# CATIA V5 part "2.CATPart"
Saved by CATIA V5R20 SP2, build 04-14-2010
Part number: 2
Bounding box of the stored display mesh (mm): x -150 to 150, y -550 to 106.066, z -75 to 75
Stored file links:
  C:\Users\Orange\Desktop\Assembly Design-14\2.CATPart
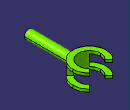
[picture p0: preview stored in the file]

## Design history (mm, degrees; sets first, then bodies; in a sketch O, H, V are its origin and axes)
Body1 (main body)
  Sketch1 on xy-plane, origin (0, 0, 0), H (1, 0, 0), V (0, 1, 0)
    circle A1 centre (0, 0) radius 150
    circle A2 centre (0, 0) radius 100
  Pad1: profile Sketch1, direction (0, 0, 1), length 75, mirrored extent
  Sketch2 on xy-plane, origin (0, 0, 0), H (1, 0, 0), V (0, 1, 0)
    line L1 (-53.5621, -53.5621) -> (-151.3863, -151.3863)
    line L2 (48.3586, 48.3586) -> (151.3863, 151.3863)
    line L3 (53.5621, -53.5621) -> (151.3863, -151.3863)
    line L4 (-48.3586, 48.3586) -> (-151.3863, 151.3863)
    line L5 (151.3863, 151.3863) -> (258.446, 0)
    line L6 (258.446, 0) -> (151.3863, -151.3863)
    line L7 (-151.3863, 151.3863) -> (-223.47, -41.262)
    line L8 (-223.47, -41.262) -> (-151.3863, -151.3863)
    line L9 (48.3586, 48.3586) -> (53.5621, -53.5621)
    line L10 (-48.3586, 48.3586) -> (-53.5621, -53.5621)
  Pocket1: profile Sketch2, direction (0, 0, -1), length 50, mirrored extent
  Sketch3 on xy-plane, origin (0, 0, 0), H (1, 0, 0), V (0, 1, 0)
    line L1 (0, 0) -> (179.9089, 179.9089)
    line L2 (0, 0) -> (-179.9089, 179.9089)
    line L3 (179.9089, 179.9089) -> (-179.9089, 179.9089)
  Pocket2: profile Sketch3, direction (0, 0, -1), length 100, mirrored extent
  Sketch4 on zx-plane, origin (0, 0, 0), H (-1, 0, 0), V (0, 0, 1)
    circle A1 centre (0, 0) radius 40
  Pad2: profile Sketch4, direction (0, -1, 0), length 550, opposite side up to face of Pad1 from Sketch1.A1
